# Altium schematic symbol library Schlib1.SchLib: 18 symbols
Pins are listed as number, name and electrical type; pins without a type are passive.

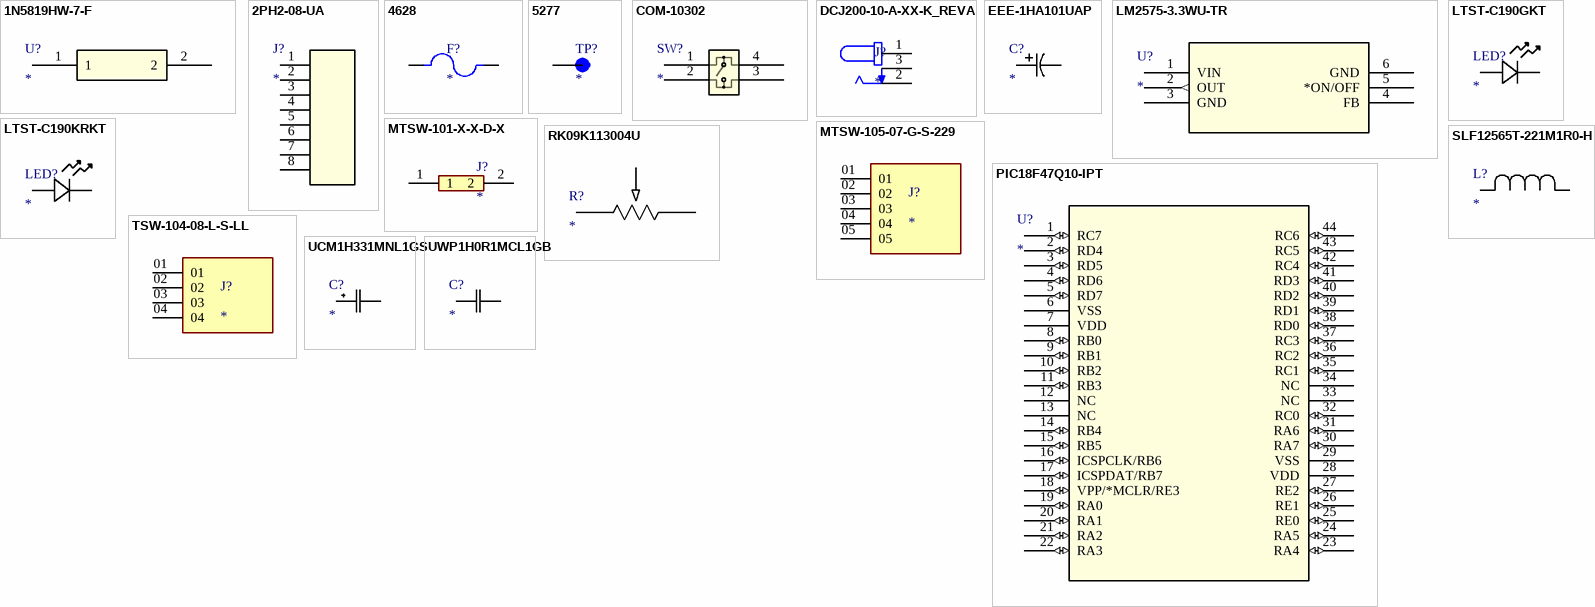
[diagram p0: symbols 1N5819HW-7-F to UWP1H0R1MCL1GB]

## 1N5819HW-7-F
designator U?
No Description Available; Mfr_Name: Diodes Inc
footprint 1N5819HW-7-F_DIO
pins: 1, 2

## 2PH2-08-UA
designator J?
No Description Available; Mfr_Name: ADAM TECHNOLOGIES INC
footprint CONN_2PH2-08-UA_ADM
pins: 1, 2, 3, 4, 5, 6, 7, 8

## 4628
designator F?
5mm Slim Line Fuse holder; MF: Keystone; MP: 4628
footprint FUSE_4628
pins: 1, 2

## 5277
designator TP?
TEST POINT (BLUE) - COMPACT; MF: Keystone Electronics; MP: 5277
footprint KEYSTONE_5277
pins: 1 TP

## COM-10302
designator SW?
No Description Available; Mfr_Name: Sparkfun
footprint COM-10302_SPK
pins: 1, 2, 3, 4

## DCJ200-10-A-XX-K_REVA
designator J?
Power Barrel Connector Jack 2.05mm ID (0.081), 5.50mm OD (0.217) Through Hole, Right Angle; MF: Global Connector Technology; MP: DCJ200-10-A-K1-K
footprint GCT_DCJ200-10-A-XX-K_REVA
pins: 1, 2, 3

## EEE-1HA101UAP
designator C?
No Description Available; Mfr_Name: Panasonic
footprint CAP_PAN_EEE_F_PAN
pins: 1, 2

## LM2575-3.3WU-TR
designator U?
No Description Available; Mfr_Name: Microchip
footprint TO-263-5T_MCH-L
pins: 1 VIN (power), 2 OUT (out), 3 GND (power), 4 FB, 5 *ON/OFF, 6 GND (power)

## LTST-C190GKT
designator LED?
No Description Available; Mfr_Name: LITE-ON
footprint LED_LTST-C190CKT_LTO
pins: 1, 2

## LTST-C190KRKT
designator LED?
No Description Available; Mfr_Name: LITE-ON; Type: LED Indication
footprint LED_LTST-C190_LTO
pins: 1 CATHODE, 2 ANODE

## MTSW-101-X-X-D-X
designator J?
Variable Height PCB Header Strips, 0.100 pitch; MF: SAMTEC; MP: MTSW-101-09-L-D-210
footprint SAMTEC_MTSW-101-X-X-D-X
pins: 1, 2

## MTSW-105-07-G-S-229
designator J?
MP: MTSW-105-07-G-S-229
footprint SAMTEC_MTSW-105-07-G-S-229
pins: 01, 02, 03, 04, 05

## PIC18F47Q10-IPT
designator U?
No Description Available; Mfr_Name: Microchip
footprint TQFP44_PT_MCH
pins: 1 RC7 (io), 2 RD4 (io), 3 RD5 (io), 4 RD6 (io), 5 RD7 (io), 6 VSS (power), 7 VDD (power), 8 RB0 (io), 9 RB1 (io), 10 RB2 (io), 11 RB3 (io), 12 NC, 13 NC, 14 RB4 (io), 15 RB5 (io), 16 ICSPCLK/RB6 (io), 17 ICSPDAT/RB7 (io), 18 VPP/*MCLR/RE3 (io), 19 RA0 (io), 20 RA1 (io), 21 RA2 (io), 22 RA3 (io), 23 RA4 (io), 24 RA5 (io), 25 RE0 (io), 26 RE1 (io), 27 RE2 (io), 28 VDD (power), 29 VSS (power), 30 RA7 (io), 31 RA6 (io), 32 RC0 (io), 33 NC, 34 NC, 35 RC1 (io), 36 RC2 (io), 37 RC3 (io), 38 RD0 (io), 39 RD1 (io), 40 RD2 (io), 41 RD3 (io), 42 RC4 (io), 43 RC5 (io), 44 RC6 (io)

## RK09K113004U
designator R?
No Description Available; Mfr_Name: Alps Electric
footprint POT_RK09K113004U_AAL
pins: 1, 2, 3

## SLF12565T-221M1R0-H
designator L?
No Description Available; Mfr_Name: TDK
footprint IND_12565_TDK
pins: 1, 2

## TSW-104-08-L-S-LL
designator J?
MP: TSW-104-08-L-S-LL
footprint SAMTEC_TSW-104-08-L-S-LL
pins: 01, 02, 03, 04

## UCM1H331MNL1GS
designator C?
No Description Available; Mfr_Name: Nichicon
footprint CAP_UCD_10X10_NCH
pins: 1, 2

## UWP1H0R1MCL1GB
designator C?
No Description Available; Mfr_Name: Nichicon
footprint CAP_UWF_4X5P4_NCH
pins: 1, 2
